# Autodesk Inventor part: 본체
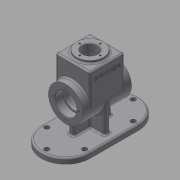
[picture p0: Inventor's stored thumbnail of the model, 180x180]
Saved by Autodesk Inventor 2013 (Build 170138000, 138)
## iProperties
Created: 2019-01
Part Number: 본체
Material: 일반
Document SubType Name: Modeling
Designer: mduedu
Density: 1 g/cm^3
Author: mduedu
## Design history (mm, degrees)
sketch "스케치1"
  geometry: C1 r 32 at (0, 0); 1 further point
  constraints: 1 centre point, 1 coincident
  dimensions: "d0" = 64 diameter of C1
extrude "돌출1" new body sketch "스케치1" stored distance "d1" = 90; taper "d2" = 0 deg
sketch "스케치2"
  geometry: L1 (0, 32)-(60, 32); L2 (60, 32)-(60, -32); L3 (60, -32)-(0, -32); L4 (0, -32)-(0, 32); C1 r 32 at (0, 0) reference; 2 further points
  constraints: 8 end point, 2 parallel, 1 coincident, 1 horizontal, 1 midpoint, 1 perpendicular, 1 tangent
  dimensions: "d5" = 60 distance between parallel lines of L4 L2
extrude "돌출2" join sketch "스케치2" stored distance "d7" = 64; taper "d8" = 0 deg
sketch "스케치3"
  geometry: C1 r 25 at (32, 32); 1 further point
  constraints: 1 centre point, 1 coincident
  dimensions: "d9" = 50 diameter of C1
extrude "돌출3" join sketch "스케치3" distance "d10" = 5; taper "d11" = 0 deg
sketch "스케치4"
  geometry: L1 (50, 25)-(0, 25); L2 (0, 25)-(0, -25); L3 (0, -25)-(50, -25); L4 (50, -25)-(50, 25); L5 (65, -25)-(65, 25) reference; A1 r 25 centre (0, 0) between (0, 25) and (0, -25); A2 r 25 centre (0, 0) between (0, -25) and (0, 25); 2 further points
  constraints: 8 end point, 4 point on circle, 2 centre point, 2 coincident, 2 parallel, 1 horizontal, 1 midpoint, 1 perpendicular, 1 tangent
  dimensions: "d12" = 50 diameter of A1; "d13" = 15 distance between parallel lines of L4 L5
extrude "돌출4" cut sketch "스케치4" stored distance "d14" = 48; taper "d15" = 0 deg
sketch "스케치5"
  geometry: C1 r 20 at (0, 0); 1 further point
  constraints: 1 centre point, 1 coincident
  dimensions: "d16" = 40 diameter of C1
extrude "돌출5" cut sketch "스케치5" distance "d17" = 15; taper "d18" = 0 deg
sketch "스케치6"
  geometry: C1 r 17 at (0, 0); 1 further point
  constraints: 1 centre point, 1 coincident
  dimensions: "d19" = 34 diameter of C1
extrude "돌출6" cut sketch "스케치6" stored distance "d20" = 15; taper "d21" = 0 deg
fillet "모깎기1" dims "d22" = 0.3
fillet "모깎기2" dims "d23" = 3
fillet "모깎기3" dims "d24" = 3
fillet "모깎기4" dims "d25" = 3
fillet "모깎기5" dims "d26" = 3
fillet "모깎기6" dims "d27" = 3
sketch "스케치7"
  geometry: C1 r 14 at (0, 0); 1 further point
  constraints: 1 centre point, 1 coincident
  dimensions: "d28" = 28 diameter of C1
extrude "돌출7" cut sketch "스케치7" stored distance "d29" = 15; taper "d30" = 0 deg
chamfer "모따기1" distance "d31" = 1; stored, may be unused: second distance "d32" = 2, angle "d33" = 45 deg
chamfer "모따기2" distance "d34" = 1; stored, may be unused: second distance "d35" = 2, angle "d36" = 45 deg
node "작업 평면1"
sketch "스케치8"
  geometry: L1 (45, 45)-(-45, 45); L2 (-45, 45)-(-45, -45); L3 (-45, -45)-(45, -45); L4 (45, -45)-(45, 45); L5 (45, 45)-(-45, -45); L6 (-45, 45)-(45, -45); A1 r 45 centre (45, 0) between (45, -45) and (45, 45); A2 r 45 centre (-45, 0) between (-45, 45) and (-45, -45); A3 r 45 centre (45, 0) between (0, 0) and (45, -45); A4 r 45 centre (45, 0) between (0, 0) and (0, 0); A5 r 45 centre (45, 0) between (45, 45) and (0, 0); A6 r 45 centre (-45, 0) between (0, 0) and (-45, 45); A7 r 45 centre (-45, 0) between (-45, -45) and (0, 0); 1 further point
  constraints: 14 point on circle, 12 end point, 7 centre point, 7 midpoint, 2 parallel, 1 horizontal, 1 perpendicular
  dimensions: "d99" = 90 distance between parallel lines of L1 L3; "d101" = 90 distance between parallel lines of L2 L4
extrude "돌출8" join sketch "스케치8" distance "d41" = 10; taper "d42" = 0 deg
sketch "스케치9"
  geometry: L1 (-35, 5)-(35, 5); L2 (35, 5)-(35, -5); L3 (35, -5)-(-35, -5); L4 (-35, -5)-(-35, 5); 3 further points
  constraints: 8 end point, 2 midpoint, 2 parallel, 1 horizontal, 1 horizontal alignment, 1 perpendicular, 1 vertical alignment
  dimensions: "d52" = 10 distance of L1.end L2.end; "d54" = 70 distance of L1.start L1.end
extrude "돌출9" join sketch "스케치9" stored distance "d50" = 10; taper "d51" = 0 deg
sketch "스케치10"
  geometry: L1 (0, -25)-(47, -25) reference; L2 (50, -22)-(50, -14) reference; L3 (50, -14)-(64, -14) reference; L4 (64, -14)-(65, -15) reference; L5 (65, -15)-(65, -25) reference; L6 (65, -25)-(63, -25) reference; L7 (60, -28)-(60, -29) reference; L8 (57, -32)-(0, -32) reference; L9 (-31.607, -5)-(-55, -5) reference; L10 (-55, -5)-(-55, -45) reference; L11 (-65, -45)-(-65, 45) reference; L12 (-55, 45)-(-55, 5) reference; L13 (-55, 5)-(-31.607, 5) reference; L14 (0, 32)-(57, 32) reference; L15 (60, 29)-(60, 28) reference; L16 (63, 25)-(65, 25) reference; L17 (65, 25)-(65, 15) reference; L18 (65, 15)-(64, 14) reference; L19 (64, 14)-(50, 14) reference; L20 (50, 14)-(50, 22) reference; L21 (47, 25)-(0, 25) reference; L22 (-55, -45)-(-65, -45) reference; L23 (-65, 45)-(-55, 45) reference; L24 (0, 32)-(-55, 32); A1 r 25 centre (0, 0) between (0, 25) and (0, -25) reference; A2 r 3 centre (47, -22) between (47, -25) and (50, -22) reference; A3 r 3 centre (63, -28) between (63, -25) and (60, -28) reference; A4 r 3 centre (57, -29) between (57, -32) and (60, -29) reference; A5 r 32 centre (0, 0) between (-31.607, -5) and (0, -32) reference; A6 r 32 centre (0, 0) between (0, 32) and (-31.607, 5) reference; A7 r 3 centre (57, 29) between (60, 29) and (57, 32) reference; A8 r 3 centre (63, 28) between (60, 28) and (63, 25) reference; A9 r 3 centre (47, 22) between (50, 22) and (47, 25) reference
  constraints: 2 end point, 1 perpendicular, 1 point on line, 1 tangent
feature "리브1" sketch "스케치10" dims "d57" = 1, "d58" = 10, "d59" = 0, "d60" = 0, "d61" = 1, "d62" = 1
fillet "모깎기7" dims "d63" = 3
fillet "모깎기11" dims "d102" = 3
fillet "모깎기8" dims "d64" = 3
sketch "스케치11"
  geometry: L1 (8, -29)-(8, -8) reference; L2 (-8, -8)-(-8, -29) reference; L3 (-32, -8)-(-8, -8) reference; L4 (-38, 2)-(-38, -2) reference; L5 (-8, 8)-(-32, 8) reference; L6 (-8, 29)-(-8, 8) reference; L7 (8, 8)-(8, 29) reference; L8 (32, 8)-(8, 8) reference; L9 (38, -2)-(38, 2) reference; L10 (8, -8)-(32, -8) reference; L11 (-2, -35)-(2, -35) reference; L12 (2, 35)-(-2, 35) reference; L13 (-45, -45)-(45, -45) reference; L14 (45, 45)-(-45, 45) reference; L15 (-45, -35)-(45, -35); L16 (45, 35)-(-45, 35); A1 r 6 centre (-32, -2) between (-38, -2) and (-32, -8) reference; A2 r 6 centre (-32, 2) between (-32, 8) and (-38, 2) reference; A3 r 6 centre (32, 2) between (38, 2) and (32, 8) reference; A4 r 6 centre (32, -2) between (32, -8) and (38, -2) reference; A5 r 6 centre (2, -29) between (2, -35) and (8, -29) reference; A6 r 6 centre (-2, -29) between (-8, -29) and (-2, -35) reference; A7 r 6 centre (-2, 29) between (-2, 35) and (-8, 29) reference; A8 r 6 centre (2, 29) between (8, 29) and (2, 35) reference; A9 r 45 centre (-45, 0) between (-45, 45) and (-45, -45) reference; A10 r 45 centre (45, 0) between (45, -45) and (45, 45) reference; A11 r 35 centre (-45, 0) between (-45, 35) and (-45, -35); A12 r 35 centre (45, 0) between (45, -35) and (45, 35); 7 further points
  constraints: 6 point on circle, 4 coincident, 4 end point, 2 centre point, 3 other
  dimensions: "d103" = 10 distance between parallel lines of L16 L14
hole "구멍1" sketch "스케치11" at (-45, 35), (-80, 0), (-45, -35), (45, -35), (80, 0), (45, 35) diameter "d66" = 9; stored, may be unused: countersink angle "d70" = 90 deg, drill point angle "d72" = 118 deg; dims "d67" = 6, "d68" = 4, "d69" = 2, "d71" = 8
fillet "모깎기10" dims "d73" = 3
sketch "스케치12"
  geometry: L1 (-3, 57)-(-3, 19.596) reference; 2 further points
  constraints: 1 other
  dimensions: "d74" = 32 distance from line of point (29, 45) L1; "d75" = 45 distance of point (29, 45) point (29, 0)
feature "엠보싱1" sketch "스케치12" dims "d12" = 50, "d13" = 15, "d76" = 0.5, "d77" = 0
sketch "스케치13"
  geometry: 4 further points
  constraints: 4 other
hole "구멍2" sketch "스케치13" at (-25, 0), (0, -25), (25, 0), (0, 25) diameter "d78" = 3.242; stored, may be unused: countersink angle "d82" = 90 deg, drill point angle "d84" = 120 deg; dims "d79" = 7, "d80" = 4, "d81" = 2, "d83" = 9
sketch "스케치14"
  geometry: 4 further points
  constraints: 4 other
hole "구멍3" sketch "스케치14" at (-25, 0), (0, -25), (25, 0), (0, 25) diameter "d85" = 3.242; stored, may be unused: countersink angle "d89" = 90 deg, drill point angle "d91" = 120 deg; dims "d86" = 7, "d87" = 4, "d88" = 2, "d90" = 9
sketch "스케치15"
  geometry: 4 further points
  constraints: 4 other
hole "구멍4" sketch "스케치15" at (0, -19), (19, 0), (0, 19), (-19, 0) diameter "d92" = 3.242; stored, may be unused: countersink angle "d96" = 90 deg, drill point angle "d98" = 120 deg; dims "d93" = 8, "d94" = 4, "d95" = 2, "d97" = 10
node "솔리드1"
mirror "대칭1"
mirror "대칭2"
node "투영된 루프1"
node "투영된 루프2"
node "절단 모서리 투영1"
node "절단 모서리 투영2"
other parameters: "d37" = -65
